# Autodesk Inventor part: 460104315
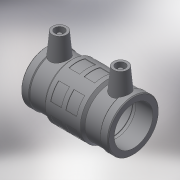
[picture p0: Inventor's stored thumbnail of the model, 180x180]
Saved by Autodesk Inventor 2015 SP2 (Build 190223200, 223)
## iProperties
Created: 2017-06
Part Number: 460104315
Material: Generic
Description: PLASSON LIGHTFIT COUPLER 315
Document SubType Name: Modeling
Designer: KIM
Mass: 89.5427 g
Surface Area: 304.58 cm^2
Volume: 89.5427 cm^3
Density: 1 g/cm^3
Appearance: Default
Author: KIM
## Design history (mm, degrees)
derived "460104.ipt"
feature "Solid1::460104.ipt"
tag "TaggingFeature1"
body "Solid1"
other parameters: "d13" = 284, "d14" = 17.6296, "d17" = 311.85, "d18" = 315, "d19" = 3.52592, "d20" = 168 deg, "d22" = 351.56, "d23" = 374, "d24" = 341.0132, "d25" = 135 deg, "d26" = 113.6, "d27" = 135 deg, "d29" = 184, "d35" = 15, "d39" = 5 deg, "d44" = 4, "d46" = 14, "d47" = 0, "d52" = 366.52, "d53" = 14.2, "d54" = 14.2, "d55" = 14.2, "d56" = 35 deg, "d58" = 360 deg, "d60" = 28, "d61" = 135 deg, "d62" = 127.8, "d63" = 3, "d64" = 0, "d_" = 315, "L_" = 284, "D_" = 374, "A_" = 184, "d_2" = 12
